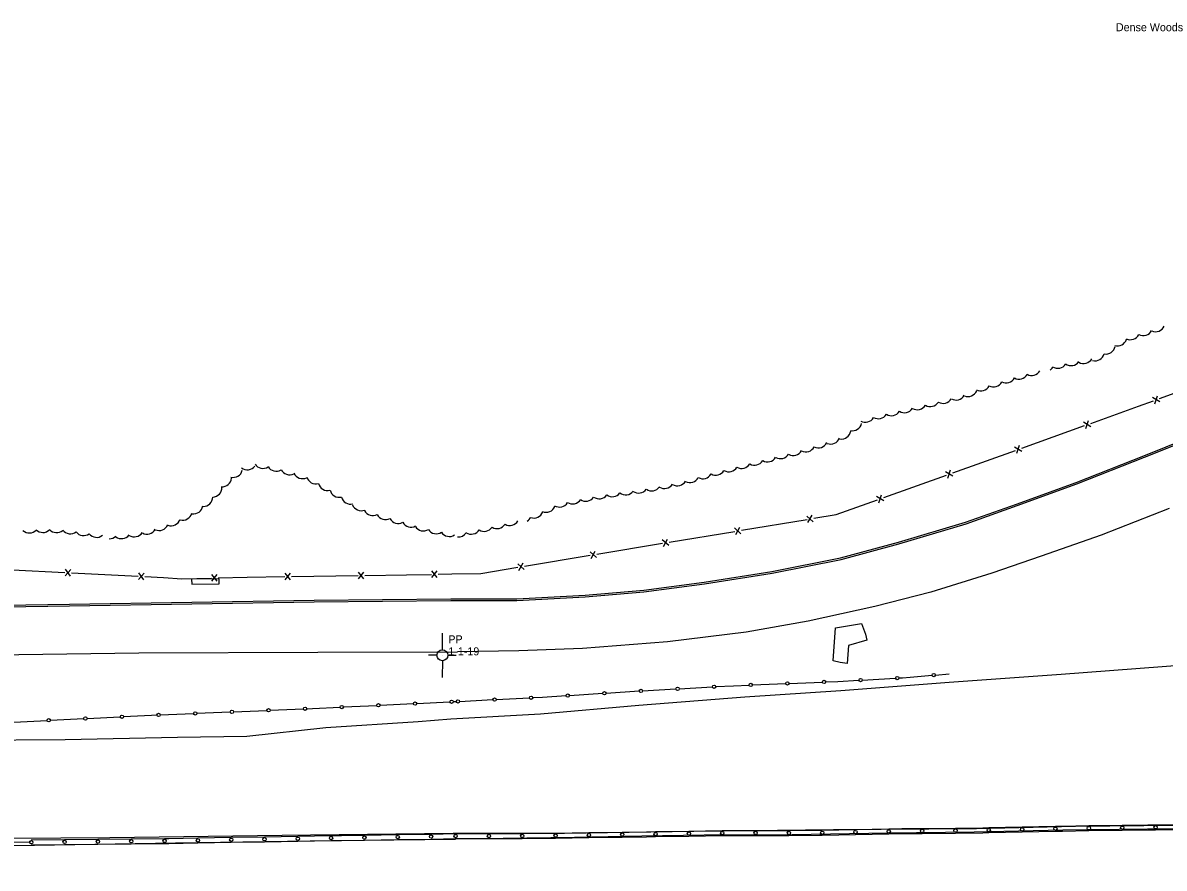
# Model space of a CAD drawing. Extents: x 2402803 to 2427059, y 6985292 to 6997652.
# Drawn here: x 2421473 to 2422158, y 6991449 to 6991956 of the extents above; entities that cross this region are included whole.
import ezdxf

# ---------------------------------------------------------------- set-up
doc = ezdxf.new("R2010")
doc.units = 0
for name, color, linetype in [('p_control ground ctrl', 7, 'Continuous'), ('p_drainage conc drain', 7, 'Continuous'), ('p_road - paved curb', 7, 'Continuous'), ('p_road bridge end', 7, 'Continuous'), ('p_road conc barrier', 7, 'Continuous'), ('p_road guard fences', 7, 'Continuous'), ('p_structure fence', 7, 'Continuous'), ('p_veg woods', 7, 'Continuous')]:
    doc.layers.add(name, color=color, linetype=linetype)

msp = doc.modelspace()

# ---------------------------------------------------------------- linework, layer by layer
at = {"layer": 'p_control ground ctrl'}
for p, q in [((2421725.12, 6991579.63), (2421725.14, 6991589.63)), ((2421721.88, 6991576.39), (2421716.88, 6991576.4)), ((2421725.12, 6991573.15), (2421725.1, 6991563.15)), ((2421725.12, 6991576.39), (2421725.12, 6991576.43)), ((2421728.36, 6991576.39), (2421733.36, 6991576.38))]:
    msp.add_line(p, q, dxfattribs=at)
msp.add_circle((2421725.12, 6991576.39), 3.24, dxfattribs=at)
at = {"layer": 'p_drainage conc drain'}
for points in [[(2421959.61, 6991573.07), (2421960.91, 6991592.86), (2421976.43, 6991595.55), (2421978.88, 6991589.1), (2421979.76, 6991585.41)], [(2421979.76, 6991585.41), (2421968.68, 6991582.19), (2421967.98, 6991571.52), (2421963.82, 6991571.99), (2421959.61, 6991573.07)]]:
    msp.add_lwpolyline(points, dxfattribs=at)
at = {"layer": 'p_road - paved curb'}
for points in [[(2421730.2, 6991610.26), (2421769.7, 6991610.36), (2421810.73, 6991612.45), (2421845.89, 6991615.54), (2421882.25, 6991620.34), (2421922.79, 6991626.61), (2421964.01, 6991634.94), (2421998.71, 6991644.33), (2422038.95, 6991656.27), (2422069.59, 6991667.15), (2422105.36, 6991680.15), (2422145.86, 6991696.19), (2422187.04, 6991712.72)], [(2421730.2, 6991609.26), (2421769.73, 6991609.36), (2421810.8, 6991611.45), (2421846, 6991614.55), (2421882.39, 6991619.35), (2421922.97, 6991625.63), (2421964.24, 6991633.97), (2421998.98, 6991643.37), (2422039.26, 6991655.32), (2422069.93, 6991666.21), (2422105.71, 6991679.22), (2422146.23, 6991695.26), (2422187.41, 6991711.79)], [(2422161.09, 6991664.4), (2422120.23, 6991648.47), (2422084.26, 6991635.96), (2422054.68, 6991625.73), (2422018.13, 6991614.34), (2421984.56, 6991605.71), (2421944.52, 6991596.84), (2421907.39, 6991590.31), (2421860.14, 6991584.53), (2421809.25, 6991580.56), (2421771.01, 6991579.1), (2421734.11, 6991578.53)], [(2420541.82, 6991594.33), (2420582.14, 6991594.56), (2420647.55, 6991594.97), (2420697.21, 6991595.96), (2420751.01, 6991596.71), (2420821.78, 6991597), (2420905.74, 6991598.54), (2420980.57, 6991599.78), (2421073.3, 6991601.14), (2421164.16, 6991601.93), (2421246.43, 6991603.52), (2421326.93, 6991604.67), (2421422.94, 6991605.79), (2421501.41, 6991607.13), (2421648.24, 6991609.38), (2421730.19, 6991610.26)], [(2420541.83, 6991593.33), (2420582.15, 6991593.56), (2420647.56, 6991593.97), (2420697.23, 6991594.96), (2420751.02, 6991595.71), (2420821.79, 6991596), (2420905.76, 6991597.54), (2420980.59, 6991598.78), (2421073.31, 6991600.14), (2421164.17, 6991600.93), (2421246.45, 6991602.52), (2421326.94, 6991603.67), (2421422.95, 6991604.79), (2421501.43, 6991606.13), (2421648.25, 6991608.38), (2421730.2, 6991609.26)], [(2421730.18, 6991538.22), (2421783.91, 6991541.31), (2421842.98, 6991546.36), (2421906.64, 6991551.54), (2421964.04, 6991555.35), (2422029.05, 6991560.34), (2422096.32, 6991565.01), (2422172.66, 6991570.84), (2422254.42, 6991576.57), (2422344.93, 6991582.24), (2422424.07, 6991587.49), (2422513.29, 6991594.29), (2422589.21, 6991598.92), (2422637.47, 6991601.07)], [(2420538.72, 6991557.93), (2420618.87, 6991559.08), (2420697.15, 6991561.37), (2420764.79, 6991564.08), (2420833.18, 6991565.78), (2420905.62, 6991566.85), (2420966.66, 6991568.62), (2421045.66, 6991570.63), (2421133.98, 6991570.8), (2421240.31, 6991573.79), (2421337.04, 6991573.87), (2421456.4, 6991576.6), (2421542.99, 6991577.82), (2421650.33, 6991578.31), (2421734.11, 6991578.53)], [(2420541.16, 6991516.6), (2420638.91, 6991513.75), (2420730.23, 6991514.17), (2420801.84, 6991514.92), (2420884.78, 6991516.09), (2420962.37, 6991517.54), (2421033.32, 6991518.59), (2421092.66, 6991519.15), (2421162.51, 6991520.13), (2421231.91, 6991520.97), (2421301.39, 6991522.27), (2421373.18, 6991522.83), (2421439.74, 6991525.36), (2421498.77, 6991525.93), (2421566.23, 6991527.22), (2421607.82, 6991527.8), (2421655.29, 6991533.07), (2421710.58, 6991536.71), (2421730.18, 6991538.22)], [(2421731.66, 6991469.62), (2421798.31, 6991469.7), (2421875.87, 6991470.84), (2421959.71, 6991471.78), (2422045.53, 6991472.48), (2422104.79, 6991473.88), (2422187.09, 6991474.64), (2422249.13, 6991476.01), (2422335.33, 6991476.81), (2422416.79, 6991477.93), (2422504.89, 6991479.07), (2422598.43, 6991480.18), (2422634.76, 6991480.7)], [(2422633.77, 6991478.23), (2422600.76, 6991478.27), (2422569.47, 6991477.37), (2422529.43, 6991477.3), (2422473.49, 6991476.04), (2422419.7, 6991475.61), (2422364.84, 6991474.51), (2422315.35, 6991473.88), (2422269.63, 6991473.72), (2422222.99, 6991473.38), (2422164.85, 6991472.15), (2422097.27, 6991471.43), (2422044.16, 6991470.23), (2421992.42, 6991469.64), (2421934.88, 6991468.66), (2421882.22, 6991468.38), (2421844.81, 6991467.91), (2421804.41, 6991467.01), (2421732.91, 6991466.08)], [(2420540.3, 6991454.31), (2420627.99, 6991455.26), (2420719.98, 6991456.21), (2420814.8, 6991457.23), (2420908.83, 6991458.67), (2420999.62, 6991459.72), (2421085.57, 6991461.47), (2421185.61, 6991462.2), (2421271.24, 6991463.31), (2421353.47, 6991464.52), (2421437.56, 6991466.49), (2421525.67, 6991467.13), (2421629.1, 6991468.51), (2421697.11, 6991469.16), (2421731.66, 6991469.62)], [(2420539.8, 6991448.62), (2420626.52, 6991449.91), (2420721.81, 6991451.24), (2420808.45, 6991452.21), (2420909.29, 6991454.51), (2420983.78, 6991455.47), (2421068.07, 6991457.1), (2421154.8, 6991457.86), (2421220.73, 6991459.48), (2421307.66, 6991460.26), (2421389.3, 6991461.73), (2421480.45, 6991462.47), (2421565.01, 6991463.91), (2421659.25, 6991465.18), (2421732.91, 6991466.08)]]:
    msp.add_lwpolyline(points, dxfattribs=at)
at = {"layer": 'p_road bridge end'}
msp.add_lwpolyline([(2421574.75, 6991619.03), (2421591.23, 6991619.2), (2421591.2, 6991622.32), (2421574.72, 6991622.15)], close=True, dxfattribs=at)
at = {"layer": 'p_road conc barrier'}
for p, q in [((2422152.88, 6991474.7), (2422172.87, 6991474.9)), ((2421638.4, 6991467.83), (2421658.39, 6991468.17)), ((2421678.38, 6991468.49), (2421698.38, 6991468.8)), ((2421698.38, 6991468.8), (2421718.37, 6991469.12)), ((2421718.37, 6991469.12), (2421733.05, 6991469.35)), ((2421733.06, 6991469.35), (2421753.06, 6991469.42)), ((2421753.06, 6991469.42), (2421773.06, 6991469.5)), ((2421793.02, 6991469.66), (2421813, 6991469.96)), ((2421813, 6991469.96), (2421832.99, 6991470.26)), ((2421852.98, 6991470.56), (2421872.97, 6991470.86)), ((2421872.97, 6991470.86), (2421892.97, 6991471.17)), ((2421873.02, 6991467.86), (2421893.01, 6991468.17)), ((2421913, 6991471.27), (2421932.99, 6991471.32)), ((2421913, 6991468.27), (2421932.99, 6991468.32)), ((2421952.92, 6991471.4), (2421972.9, 6991471.8)), ((2421952.98, 6991468.4), (2421972.96, 6991468.8)), ((2421972.9, 6991471.8), (2421992.88, 6991472.2)), ((2421972.96, 6991468.8), (2421992.94, 6991469.2)), ((2422012.89, 6991472.5), (2422032.89, 6991472.72)), ((2422012.93, 6991469.5), (2422032.92, 6991469.72)), ((2422052.86, 6991472.98), (2422072.85, 6991473.4)), ((2422052.92, 6991469.98), (2422072.92, 6991470.4)), ((2422072.85, 6991473.4), (2422092.85, 6991473.82)), ((2422072.92, 6991470.4), (2422092.91, 6991470.82)), ((2422112.87, 6991474.14), (2422132.86, 6991474.43)), ((2422112.91, 6991471.14), (2422132.91, 6991471.43)), ((2422152.91, 6991471.7), (2422172.9, 6991471.9)), ((2421478.48, 6991465.7), (2421498.47, 6991465.9)), ((2421478.51, 6991462.7), (2421498.5, 6991462.9)), ((2421498.47, 6991465.9), (2421518.47, 6991466.1)), ((2421498.5, 6991462.9), (2421518.5, 6991463.1)), ((2421518.47, 6991466.1), (2421538.47, 6991466.3)), ((2421518.5, 6991463.1), (2421538.5, 6991463.3)), ((2421538.47, 6991466.3), (2421558.47, 6991466.5)), ((2421538.5, 6991463.3), (2421558.5, 6991463.5)), ((2421578.43, 6991466.82), (2421598.42, 6991467.16)), ((2421578.49, 6991463.82), (2421598.47, 6991464.16)), ((2421598.42, 6991467.16), (2421618.41, 6991467.49)), ((2421598.47, 6991464.16), (2421618.46, 6991464.5)), ((2421618.41, 6991467.49), (2421638.4, 6991467.83)), ((2421618.46, 6991464.5), (2421638.45, 6991464.83)), ((2421638.45, 6991464.83), (2421658.44, 6991465.17)), ((2421678.43, 6991465.49), (2421698.42, 6991465.8)), ((2421698.42, 6991465.8), (2421718.42, 6991466.12)), ((2421718.42, 6991466.12), (2421733.09, 6991466.35)), ((2421733.08, 6991466.35), (2421753.07, 6991466.42)), ((2421753.07, 6991466.42), (2421773.07, 6991466.5)), ((2421793.06, 6991466.66), (2421813.05, 6991466.96)), ((2421813.05, 6991466.96), (2421833.03, 6991467.26)), ((2421853.02, 6991467.56), (2421873.02, 6991467.86))]:
    msp.add_line(p, q, dxfattribs=at)
for points in [[(2421658.39, 6991468.17), (2421664.55, 6991468.27), (2421678.38, 6991468.49)], [(2421773.06, 6991469.5), (2421784.83, 6991469.54), (2421793.02, 6991469.66)], [(2421832.99, 6991470.26), (2421847.58, 6991470.48), (2421852.98, 6991470.56)], [(2421892.97, 6991471.17), (2421897.19, 6991471.23), (2421913, 6991471.27)], [(2421893.01, 6991468.17), (2421897.21, 6991468.23), (2421913, 6991468.27)], [(2421932.99, 6991471.32), (2421951.58, 6991471.37), (2421952.92, 6991471.4)], [(2421932.99, 6991468.32), (2421951.62, 6991468.37), (2421952.98, 6991468.4)], [(2421992.88, 6991472.2), (2422000.72, 6991472.36), (2422012.89, 6991472.5)], [(2421992.94, 6991469.2), (2422000.76, 6991469.36), (2422012.93, 6991469.5)], [(2422032.89, 6991472.72), (2422049.25, 6991472.9), (2422052.86, 6991472.98)], [(2422032.92, 6991469.72), (2422049.3, 6991469.9), (2422052.92, 6991469.98)], [(2422092.85, 6991473.82), (2422097.08, 6991473.91), (2422112.87, 6991474.14)], [(2422092.91, 6991470.82), (2422097.14, 6991470.91), (2422112.91, 6991471.14)], [(2422132.86, 6991474.43), (2422148.31, 6991474.65), (2422152.88, 6991474.7)], [(2422132.91, 6991471.43), (2422148.35, 6991471.65), (2422152.91, 6991471.7)], [(2421558.47, 6991466.5), (2421560.98, 6991466.53), (2421578.43, 6991466.82)], [(2421558.5, 6991463.5), (2421561.02, 6991463.53), (2421578.49, 6991463.82)], [(2421658.44, 6991465.17), (2421664.6, 6991465.27), (2421678.43, 6991465.49)], [(2421773.07, 6991466.5), (2421784.85, 6991466.54), (2421793.06, 6991466.66)], [(2421833.03, 6991467.26), (2421847.62, 6991467.48), (2421853.02, 6991467.56)]]:
    msp.add_lwpolyline(points, dxfattribs=at)
for centre in [(2421678.4, 6991466.99), (2421698.4, 6991467.3), (2421718.39, 6991467.62), (2421733.07, 6991467.85), (2421753.07, 6991467.92), (2421773.07, 6991468), (2421793.04, 6991468.16), (2421813.03, 6991468.46), (2421833.01, 6991468.76), (2421853, 6991469.06), (2421872.99, 6991469.36), (2421892.99, 6991469.67), (2421913, 6991469.77), (2421932.99, 6991469.82), (2421952.95, 6991469.9), (2421972.93, 6991470.3), (2421992.91, 6991470.7), (2422012.91, 6991471), (2422032.91, 6991471.22), (2422052.89, 6991471.48), (2422072.89, 6991471.9), (2422092.88, 6991472.32), (2422112.89, 6991472.64), (2422132.89, 6991472.93), (2422152.89, 6991473.2), (2421478.49, 6991464.2), (2421498.49, 6991464.4), (2421518.49, 6991464.6), (2421538.48, 6991464.8), (2421558.48, 6991465), (2421578.46, 6991465.32), (2421598.45, 6991465.66), (2421618.44, 6991465.99), (2421638.42, 6991466.33), (2421658.41, 6991466.67)]:
    msp.add_circle(centre, 1, dxfattribs=at)
at = {"layer": 'p_road guard fences'}
for p, q in [((2422020.88, 6991564.56), (2422029.16, 6991565.31)), ((2421867.18, 6991556.32), (2421887.13, 6991557.45)), ((2421911.1, 6991558.63), (2421931.08, 6991559.44)), ((2421933.07, 6991559.52), (2421953.06, 6991560.34)), ((2421977.01, 6991561.56), (2421996.96, 6991562.7)), ((2421757.4, 6991549.87), (2421777.37, 6991550.89)), ((2421801.33, 6991552.31), (2421821.28, 6991553.57)), ((2421823.28, 6991553.7), (2421843.24, 6991554.96)), ((2421845.23, 6991555.08), (2421865.19, 6991556.21)), ((2421599.86, 6991542.49), (2421619.84, 6991543.33)), ((2421621.83, 6991543.41), (2421641.81, 6991544.25)), ((2421665.78, 6991545.37), (2421685.75, 6991546.34)), ((2421687.75, 6991546.43), (2421707.72, 6991547.4)), ((2421709.72, 6991547.5), (2421729.69, 6991548.46)), ((2421731.68, 6991548.56), (2421733.74, 6991548.66)), ((2421735.43, 6991548.75), (2421755.4, 6991549.77)), ((2421468.03, 6991536.32), (2421488, 6991537.31)), ((2421490, 6991537.41), (2421509.97, 6991538.41)), ((2421511.97, 6991538.5), (2421531.94, 6991539.5)), ((2421555.91, 6991540.65), (2421575.88, 6991541.48)), ((2421577.88, 6991541.57), (2421597.86, 6991542.4)), ((2421462.63, 6991464.16), (2421478.01, 6991464.4))]:
    msp.add_line(p, q, dxfattribs=at)
for points in [[(2421998.95, 6991562.81), (2422001.06, 6991562.93), (2422005.62, 6991563.19), (2422018.88, 6991564.38)], [(2421889.13, 6991557.56), (2421899.69, 6991558.16), (2421909.1, 6991558.54)], [(2421955.05, 6991560.42), (2421962.32, 6991560.72), (2421975.01, 6991561.44)], [(2421779.37, 6991550.99), (2421785.28, 6991551.29), (2421799.33, 6991552.18)], [(2421643.81, 6991544.33), (2421647.15, 6991544.47), (2421663.78, 6991545.27)], [(2421533.94, 6991539.6), (2421550.72, 6991540.43), (2421553.91, 6991540.56)]]:
    msp.add_lwpolyline(points, dxfattribs=at)
for centre in [(2422019.88, 6991564.47), (2421866.18, 6991556.26), (2421888.13, 6991557.51), (2421910.1, 6991558.59), (2421932.08, 6991559.48), (2421954.06, 6991560.38), (2421976.01, 6991561.5), (2421997.96, 6991562.75), (2421756.4, 6991549.82), (2421778.37, 6991550.94), (2421800.33, 6991552.24), (2421822.28, 6991553.63), (2421844.23, 6991555.02), (2421598.86, 6991542.45), (2421620.84, 6991543.37), (2421642.81, 6991544.29), (2421664.78, 6991545.32), (2421686.75, 6991546.39), (2421708.72, 6991547.45), (2421730.68, 6991548.51), (2421734.43, 6991548.7), (2421489, 6991537.36), (2421510.97, 6991538.45), (2421532.94, 6991539.55), (2421554.91, 6991540.61), (2421576.88, 6991541.53)]:
    msp.add_circle(centre, 1, dxfattribs=at)
at = {"layer": 'p_structure fence'}
for p, q in [((2422155.37, 6991730.5), (2422192.91, 6991744.23)), ((2422155.49, 6991728.45), (2422151.11, 6991731.1)), ((2422152.49, 6991727.35), (2422154.12, 6991732.2)), ((2422114.12, 6991713.52), (2422109.76, 6991716.21)), ((2422111.11, 6991712.44), (2422112.77, 6991717.29)), ((2422072.63, 6991700.74), (2422110.25, 6991714.23)), ((2422072.73, 6991698.69), (2422068.37, 6991701.37)), ((2422069.72, 6991697.61), (2422071.38, 6991702.45)), ((2422031.23, 6991685.9), (2422068.86, 6991699.39)), ((2422028.33, 6991682.77), (2422029.99, 6991687.61)), ((2421989.84, 6991671.07), (2422027.47, 6991684.56)), ((2422031.34, 6991683.85), (2422026.98, 6991686.53)), ((2421989.95, 6991669.01), (2421985.58, 6991671.7)), ((2421986.93, 6991667.93), (2421988.6, 6991672.78)), ((2421947.58, 6991656.56), (2421943.77, 6991659.98)), ((2421944.42, 6991656.04), (2421946.93, 6991660.5)), ((2421904.23, 6991649.38), (2421900.42, 6991652.8)), ((2421901.07, 6991648.86), (2421903.57, 6991653.33)), ((2421904.49, 6991651.42), (2421943.9, 6991657.95)), ((2421857.71, 6991641.68), (2421860.22, 6991646.15)), ((2421861.14, 6991644.24), (2421900.55, 6991650.77)), ((2421817.78, 6991637.06), (2421857.19, 6991643.59)), ((2421860.87, 6991642.2), (2421857.06, 6991645.62)), ((2421774.43, 6991629.88), (2421813.84, 6991636.41)), ((2421817.52, 6991635.02), (2421813.71, 6991638.45)), ((2421814.36, 6991634.5), (2421816.86, 6991638.97)), ((2421498.83, 6991624.13), (2421502.23, 6991627.97)), ((2421502.03, 6991623.97), (2421499.04, 6991628.13)), ((2421502.73, 6991625.91), (2421542.68, 6991623.89)), ((2421542.78, 6991621.91), (2421546.18, 6991625.75)), ((2421545.97, 6991621.75), (2421542.98, 6991625.91)), ((2421634.04, 6991621.69), (2421630.79, 6991625.65)), ((2421630.84, 6991621.65), (2421633.98, 6991625.69)), ((2421678.03, 6991622.3), (2421674.78, 6991626.26)), ((2421674.83, 6991622.26), (2421677.98, 6991626.3)), ((2421722.03, 6991623.07), (2421718.74, 6991626.99)), ((2421718.83, 6991623), (2421721.94, 6991627.06)), ((2421774.16, 6991627.84), (2421770.35, 6991631.27)), ((2421771, 6991627.32), (2421773.51, 6991631.79)), ((2421590.07, 6991620.89), (2421586.77, 6991624.81)), ((2421586.87, 6991620.81), (2421589.97, 6991624.89)), ((2421634.61, 6991623.67), (2421674.61, 6991624.23)), ((2421722.58, 6991625.05), (2421730.82, 6991625.23))]:
    msp.add_line(p, q, dxfattribs=at)
for points in [[(2422114.02, 6991715.58), (2422142.69, 6991725.86), (2422151.62, 6991729.13)], [(2421947.85, 6991658.6), (2421961.26, 6991660.82), (2421986.08, 6991669.72)], [(2421458.78, 6991628.08), (2421467.32, 6991627.7), (2421498.73, 6991626.11)], [(2421730.82, 6991625.23), (2421748.19, 6991625.54), (2421770.48, 6991629.23)], [(2421546.67, 6991623.69), (2421557.9, 6991623.12), (2421568.83, 6991622.34), (2421586.62, 6991622.77)], [(2421590.62, 6991622.87), (2421608.13, 6991623.3), (2421630.61, 6991623.61)], [(2421678.61, 6991624.28), (2421703.6, 6991624.63), (2421718.59, 6991624.96)]]:
    msp.add_lwpolyline(points, dxfattribs=at)
at = {"layer": 'p_veg woods'}
for centre, start, end in [((2422145.54, 6991773.88), 242.53766, 332.53766), ((2422152.87, 6991776.23), 246.93404, 336.93404), ((2422130.04, 6991767.69), 253.03948, 343.03948), ((2422137.9, 6991771.44), 242.84747, 332.84747), ((2422116.55, 6991758.76), 255.60791, 345.60791), ((2422123.11, 6991762.78), 259.92752, 349.92752), ((2422086.31, 6991752.05), 307.73453, 330.30109), ((2422094.24, 6991754.28), 236.93518, 326.93518), ((2422102.21, 6991755.87), 235.00421, 325.00421), ((2422109.79, 6991757.15), 239.58688, 329.58688), ((2422063.32, 6991745.52), 241.33097, 331.33097), ((2422070.96, 6991747.77), 240.74236, 330.74236), ((2422078.61, 6991749.93), 240.45443, 330.45443), ((2422040.37, 6991737.31), 248.02144, 338.02144), ((2422048.03, 6991740.68), 242.97669, 332.97669), ((2422055.68, 6991743.17), 242.05274, 332.05274), ((2422017.79, 6991731.31), 239.0481, 329.0481), ((2422025.52, 6991733.21), 239.62576, 329.62576), ((2422033.22, 6991735.22), 240.19304, 330.19304), ((2421994.51, 6991725.83), 237.79623, 327.79623), ((2422002.3, 6991727.6), 238.03696, 328.03696), ((2422010.03, 6991729.41), 238.86171, 328.86171), ((2421971.05, 6991716.76), 258.05629, 348.05629), ((2421978.8, 6991721.86), 240.774, 330.774), ((2421986.69, 6991724), 238.27849, 328.27849), ((2421964.5, 6991711.84), 260.79149, 350.79149), ((2421943.15, 6991704.16), 242.44015, 332.44015), ((2421950.68, 6991706.54), 243.8552, 333.8552), ((2421957.99, 6991708.79), 249.08116, 339.08116), ((2421920.17, 6991698.08), 239.32633, 329.32633), ((2421927.9, 6991700.04), 239.62477, 329.62477), ((2421935.55, 6991701.97), 241.17598, 331.17598), ((2421599.64, 6991688.8), 255.7025, 345.7025), ((2421608.11, 6991693.38), 232.96651, 322.96651), ((2421617.45, 6991694.23), 213.5775, 303.5775), ((2421625.48, 6991692.49), 210.32834, 300.32834), ((2421633.4, 6991690.39), 207.42973, 297.42973), ((2421889.15, 6991690.13), 239.7333, 329.7333), ((2421896.91, 6991692.16), 239.46735, 329.46735), ((2421904.67, 6991694.15), 239.21723, 329.21723), ((2421912.42, 6991696.11), 239.21723, 329.21723), ((2421593.07, 6991683.21), 264.32491, 354.32491), ((2421641.24, 6991688.09), 204.81242, 294.81242), ((2421649.26, 6991684.88), 195.44501, 285.44501), ((2421866.08, 6991683.77), 239.35398, 329.35397), ((2421873.69, 6991685.7), 241.32762, 331.32762), ((2421881.4, 6991688), 240.41314, 330.41314), ((2421587.24, 6991677), 271.57313, 1.57313), ((2421656.25, 6991680.91), 194.79782, 284.79782), ((2421663.22, 6991676.87), 193.9487, 283.9487), ((2421827.12, 6991677.23), 232.99475, 322.99475), ((2421835.03, 6991678.31), 232.99801, 322.99801), ((2421842.85, 6991679.38), 234.35892, 324.35892), ((2421850.64, 6991680.67), 235.81394, 325.81394), ((2421858.4, 6991682.14), 237.23901, 327.23901), ((2421581.74, 6991671.38), 269.72878, 359.72878), ((2421670.04, 6991672.74), 194.29585, 284.29585), ((2421676.46, 6991668.82), 201.36194, 291.36194), ((2421795.38, 6991670.98), 238.53627, 328.53627), ((2421803.28, 6991672.88), 236.59883, 326.59883), ((2421811.21, 6991674.51), 235.18352, 325.18352), ((2421819.14, 6991675.95), 234.20106, 324.20106), ((2421569.28, 6991663.07), 255.46162, 345.46162), ((2421575.84, 6991666.9), 261.39456, 351.39456), ((2421683.41, 6991665.83), 207.63798, 297.63797), ((2421691.01, 6991663.47), 208.29707, 298.29707), ((2421780.05, 6991664.4), 249.78045, 339.78045), ((2421787.39, 6991667.87), 247.19921, 337.19921), ((2421555.21, 6991656.94), 246.36054, 336.36054), ((2421562.39, 6991659.74), 250.4557, 340.4557), ((2421698.65, 6991661.18), 208.60606, 298.60606), ((2421706.32, 6991658.95), 208.77046, 298.77046), ((2421713.73, 6991656.67), 212.35883, 302.35883), ((2421750.23, 6991656.41), 237.21263, 327.21263), ((2421757.89, 6991658.05), 238.75474, 328.75474), ((2421765.58, 6991659.93), 239.49955, 329.49955), ((2421772.92, 6991661.61), 303.89548, 335.81846), ((2421477.37, 6991655.44), 226.4899, 316.4899), ((2421485.49, 6991655.73), 224.6236, 314.6236), ((2421493.77, 6991655.64), 220.61465, 310.61465), ((2421501.98, 6991654.95), 217.25952, 307.25952), ((2421509.91, 6991653.87), 217.25952, 307.25952), ((2421517.73, 6991652.81), 218.84431, 308.84431), ((2421525.21, 6991651.92), 271.19539, 315.65329), ((2421532.75, 6991652.04), 232.40965, 322.40965), ((2421540.33, 6991653.11), 237.34921, 327.34921), ((2421547.85, 6991654.76), 241.65267, 331.65267), ((2421721.49, 6991654.97), 213.09956, 303.09956), ((2421729.32, 6991653.32), 213.09956, 303.09956), ((2421734.76, 6991653.06), 263.79086, 327.21263), ((2421742.49, 6991654.73), 237.21263, 327.21263)]:
    msp.add_arc(centre, 5.65, start, end, dxfattribs=at)

# ---------------------------------------------------------------- texts
at = {"layer": 'p_control ground ctrl'}
for s, p in [('  PP', (2421725.14, 6991583.56)), ('  1-1-19', (2421725.14, 6991576.36))]:
    msp.add_text(s, height=4.8, dxfattribs=at).set_placement(p)
at = {"layer": 'p_veg woods'}
msp.add_text('Dense Woods', height=4.8, dxfattribs=at).set_placement((2422129.13, 6991950.92))

doc.saveas('drawing.dxf')
